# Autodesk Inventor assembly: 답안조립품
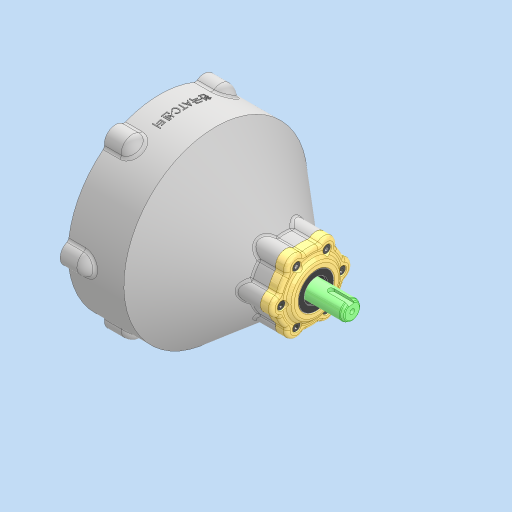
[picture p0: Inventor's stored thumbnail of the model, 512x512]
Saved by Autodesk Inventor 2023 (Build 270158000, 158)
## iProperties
Created: 2026-05
Part Number: 답안조립품
Document SubType Name: Assembly
Designer: home
Author: home
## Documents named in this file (19)
- C:\Users\home\Desktop\760503v1006\답안조립품.iam
- C:\Users\home\Desktop\760503v1006\본체.ipt
- C:\Users\home\Desktop\760503v1006\깊은 홈 볼 베어링 6203.ipt
- C:\Users\home\Desktop\760503v1006\선 기어 축.ipt
- C:\Users\home\Desktop\760503v1006\축용 C형 멈춤링 17.ipt
- C:\Users\home\Desktop\760503v1006\커버.ipt
- C:\Users\home\Desktop\760503v1006\오일 실 17 32 8.ipt
- C:\Users\home\Desktop\760503v1006\깊은 홈 볼 베어링 6010.ipt
- C:\Users\home\Desktop\760503v1006\유성 캐리어.ipt
- C:\Users\home\Desktop\760503v1006\엔드 캡.ipt
- C:\Users\home\Desktop\760503v1006\칼라.ipt
- C:\Users\home\Desktop\760503v1006\유성 캐리어 커버.ipt
- C:\Users\home\Desktop\760503v1006\유성 축.ipt
- C:\Users\home\Desktop\760503v1006\유성 기어.ipt
- C:\Users\home\Desktop\760503v1006\깊은 홈 볼 베어링 6900.ipt
- C:\Users\home\Desktop\760503v1006\링 기어.ipt
- C:\Users\home\Desktop\760503v1006\6각 구멍붙이 볼트 M4x20.ipt
- C:\Users\home\Desktop\760503v1006\6각 구멍붙이 볼트 M6x10.ipt
- C:\Users\home\Desktop\760503v1006\6각 구멍붙이 볼트 M4x10.ipt
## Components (15 placed, 3 different names)
1. 6각 구멍붙이 볼트 M4x20:1
2. 6각 구멍붙이 볼트 M4x20:2
3. 6각 구멍붙이 볼트 M4x20:3
4. 6각 구멍붙이 볼트 M4x20:4
5. 6각 구멍붙이 볼트 M4x20:5
6. 6각 구멍붙이 볼트 M4x20:6
7. 6각 구멍붙이 볼트 M6x10:1
8. 6각 구멍붙이 볼트 M6x10:2
9. 6각 구멍붙이 볼트 M6x10:3
10. 6각 구멍붙이 볼트 M4x10:1
11. 6각 구멍붙이 볼트 M4x10:2
12. 6각 구멍붙이 볼트 M4x10:3
13. 6각 구멍붙이 볼트 M4x10:4
14. 6각 구멍붙이 볼트 M4x10:5
15. 6각 구멍붙이 볼트 M4x10:6
